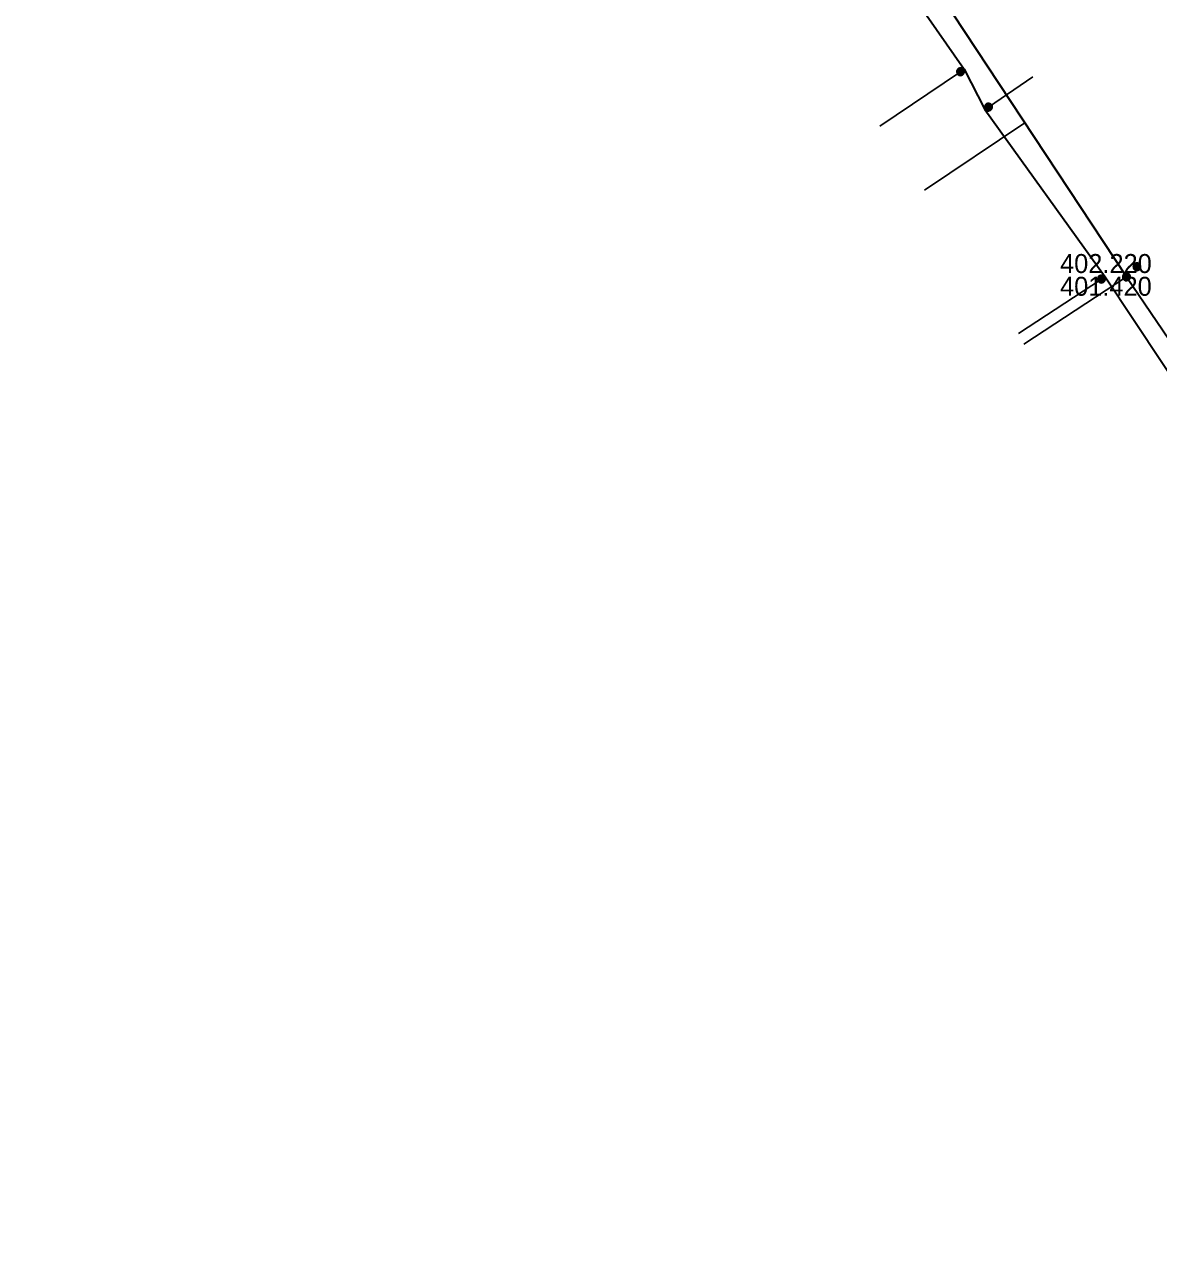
# Model space of a CAD drawing. Extents: x -873619 to -867639, y -1015082 to -1012326.
# Drawn here: x -867979.2 to -867913.4, y -1012931.2 to -1012860 of the extents above; entities that cross this region are included whole.
import ezdxf

# ---------------------------------------------------------------- set-up
doc = ezdxf.new("R2010")
doc.units = 0
doc.header["$LTSCALE"] = 0.44
for name, color, linetype, lineweight in [('1', 7, 'Continuous', 13), ('12', 7, 'Continuous', 13), ('21', 7, 'Continuous', 35), ('23', 7, 'Continuous', 25), ('25', 7, 'Continuous', 13), ('3', 7, 'Continuous', 25), ('32', 7, 'Continuous', 13)]:
    doc.layers.add(name, color=color, linetype=linetype, lineweight=lineweight)

msp = doc.modelspace()

# ---------------------------------------------------------------- linework, layer by layer
at = {"layer": '1', "lineweight": 35}
msp.add_lwpolyline([(-867979.181, -1012799.683), (-867972.83, -1012801.89), (-867965.59, -1012804.78), (-867963.787, -1012807.409), (-867948.768, -1012827.087), (-867948.538, -1012827.407), (-867943.513, -1012834.828), (-867938.476, -1012842.701), (-867934.013, -1012848.778), (-867931.689, -1012852.506), (-867924.702, -1012862.569), (-867923.496, -1012864.901), (-867916.531, -1012874.592), (-867908.231, -1012887.091), (-867905.717, -1012890.99), (-867899.122, -1012900.29), (-867892.55, -1012910.082), (-867889.71, -1012914.412), (-867888.18, -1012916.7), (-867891.84, -1012919), (-867886.89, -1012927.31), (-867886.728, -1012931.158)], dxfattribs=at)
at = {"layer": '12'}
for points in [[(-867924.679, -1012862.71), (-867924.685, -1012862.658), (-867924.702, -1012862.608), (-867924.731, -1012862.564), (-867924.768, -1012862.527), (-867924.813, -1012862.5), (-867924.863, -1012862.483), (-867924.916, -1012862.479), (-867924.968, -1012862.486), (-867925.017, -1012862.505), (-867925.06, -1012862.534), (-867925.096, -1012862.573), (-867925.122, -1012862.618), (-867925.138, -1012862.669), (-867925.141, -1012862.721), (-867925.133, -1012862.773), (-867925.113, -1012862.822), (-867925.082, -1012862.865), (-867925.043, -1012862.899), (-867924.997, -1012862.925), (-867924.946, -1012862.939), (-867924.893, -1012862.941), (-867924.842, -1012862.931), (-867924.794, -1012862.91), (-867924.751, -1012862.879), (-867924.717, -1012862.838), (-867924.693, -1012862.792), (-867924.681, -1012862.741)], [(-867924.709, -1012862.71), (-867924.715, -1012862.661), (-867924.732, -1012862.615), (-867924.76, -1012862.575), (-867924.797, -1012862.543), (-867924.841, -1012862.521), (-867924.889, -1012862.51), (-867924.938, -1012862.51), (-867924.985, -1012862.523), (-867925.028, -1012862.547), (-867925.064, -1012862.58), (-867925.091, -1012862.621), (-867925.107, -1012862.668), (-867925.111, -1012862.717), (-867925.104, -1012862.765), (-867925.085, -1012862.81), (-867925.055, -1012862.85), (-867925.017, -1012862.881), (-867924.973, -1012862.901), (-867924.925, -1012862.911), (-867924.876, -1012862.909), (-867924.829, -1012862.894), (-867924.786, -1012862.869), (-867924.752, -1012862.835), (-867924.726, -1012862.793), (-867924.712, -1012862.746)], [(-867924.739, -1012862.71), (-867924.745, -1012862.665), (-867924.762, -1012862.623), (-867924.79, -1012862.588), (-867924.826, -1012862.561), (-867924.868, -1012862.544), (-867924.913, -1012862.539), (-867924.958, -1012862.545), (-867924.999, -1012862.564), (-867925.034, -1012862.592), (-867925.061, -1012862.629), (-867925.077, -1012862.671), (-867925.081, -1012862.716), (-867925.074, -1012862.761), (-867925.055, -1012862.802), (-867925.026, -1012862.836), (-867924.989, -1012862.862), (-867924.946, -1012862.878), (-867924.901, -1012862.881), (-867924.856, -1012862.873), (-867924.816, -1012862.853), (-867924.782, -1012862.824), (-867924.756, -1012862.786), (-867924.742, -1012862.743)], [(-867924.769, -1012862.71), (-867924.774, -1012862.669), (-867924.792, -1012862.632), (-867924.819, -1012862.601), (-867924.854, -1012862.58), (-867924.894, -1012862.569), (-867924.935, -1012862.571), (-867924.974, -1012862.584), (-867925.008, -1012862.608), (-867925.033, -1012862.64), (-867925.048, -1012862.678), (-867925.051, -1012862.719), (-867925.043, -1012862.759), (-867925.023, -1012862.795), (-867924.994, -1012862.824), (-867924.957, -1012862.843), (-867924.917, -1012862.851), (-867924.876, -1012862.847), (-867924.838, -1012862.832), (-867924.806, -1012862.806), (-867924.783, -1012862.772), (-867924.77, -1012862.733)], [(-867924.799, -1012862.71), (-867924.804, -1012862.674), (-867924.822, -1012862.642), (-867924.848, -1012862.617), (-867924.882, -1012862.602), (-867924.918, -1012862.599), (-867924.953, -1012862.607), (-867924.984, -1012862.627), (-867925.007, -1012862.655), (-867925.02, -1012862.689), (-867925.02, -1012862.726), (-867925.009, -1012862.761), (-867924.988, -1012862.79), (-867924.958, -1012862.811), (-867924.923, -1012862.821), (-867924.886, -1012862.819), (-867924.852, -1012862.805), (-867924.825, -1012862.782), (-867924.806, -1012862.75), (-867924.799, -1012862.715)], [(-867924.829, -1012862.71), (-867924.834, -1012862.679), (-867924.851, -1012862.653), (-867924.877, -1012862.636), (-867924.907, -1012862.629), (-867924.938, -1012862.633), (-867924.965, -1012862.65), (-867924.983, -1012862.674), (-867924.991, -1012862.705), (-867924.987, -1012862.735), (-867924.972, -1012862.763), (-867924.948, -1012862.782), (-867924.918, -1012862.791), (-867924.887, -1012862.788), (-867924.859, -1012862.774), (-867924.839, -1012862.75), (-867924.829, -1012862.721)], [(-867924.859, -1012862.71), (-867924.864, -1012862.686), (-867924.881, -1012862.668), (-867924.904, -1012862.659), (-867924.928, -1012862.662), (-867924.949, -1012862.676), (-867924.96, -1012862.698), (-867924.96, -1012862.723), (-867924.948, -1012862.744), (-867924.928, -1012862.758), (-867924.903, -1012862.761), (-867924.88, -1012862.752), (-867924.864, -1012862.734)], [(-867924.889, -1012862.71), (-867924.894, -1012862.695), (-867924.909, -1012862.689), (-867924.924, -1012862.693), (-867924.931, -1012862.707), (-867924.927, -1012862.722), (-867924.914, -1012862.731), (-867924.899, -1012862.728), (-867924.889, -1012862.716)], [(-867923.059, -1012864.759), (-867923.066, -1012864.707), (-867923.083, -1012864.657), (-867923.112, -1012864.613), (-867923.149, -1012864.576), (-867923.194, -1012864.549), (-867923.244, -1012864.532), (-867923.297, -1012864.528), (-867923.348, -1012864.535), (-867923.397, -1012864.554), (-867923.441, -1012864.583), (-867923.477, -1012864.622), (-867923.503, -1012864.667), (-867923.519, -1012864.718), (-867923.522, -1012864.77), (-867923.514, -1012864.822), (-867923.494, -1012864.871), (-867923.463, -1012864.914), (-867923.424, -1012864.948), (-867923.378, -1012864.974), (-867923.326, -1012864.988), (-867923.274, -1012864.99), (-867923.223, -1012864.98), (-867923.174, -1012864.959), (-867923.132, -1012864.928), (-867923.098, -1012864.887), (-867923.074, -1012864.841), (-867923.061, -1012864.79)], [(-867923.09, -1012864.759), (-867923.096, -1012864.71), (-867923.113, -1012864.664), (-867923.141, -1012864.624), (-867923.178, -1012864.592), (-867923.222, -1012864.57), (-867923.27, -1012864.559), (-867923.319, -1012864.559), (-867923.365, -1012864.572), (-867923.409, -1012864.596), (-867923.445, -1012864.629), (-867923.472, -1012864.67), (-867923.488, -1012864.717), (-867923.492, -1012864.766), (-867923.485, -1012864.814), (-867923.466, -1012864.859), (-867923.436, -1012864.899), (-867923.397, -1012864.93), (-867923.353, -1012864.95), (-867923.306, -1012864.96), (-867923.257, -1012864.958), (-867923.21, -1012864.943), (-867923.167, -1012864.918), (-867923.132, -1012864.884), (-867923.107, -1012864.842), (-867923.093, -1012864.795)], [(-867923.12, -1012864.759), (-867923.125, -1012864.714), (-867923.142, -1012864.672), (-867923.171, -1012864.637), (-867923.206, -1012864.61), (-867923.249, -1012864.593), (-867923.294, -1012864.588), (-867923.338, -1012864.594), (-867923.38, -1012864.613), (-867923.414, -1012864.641), (-867923.441, -1012864.678), (-867923.458, -1012864.72), (-867923.462, -1012864.765), (-867923.455, -1012864.81), (-867923.436, -1012864.851), (-867923.407, -1012864.885), (-867923.37, -1012864.911), (-867923.326, -1012864.927), (-867923.282, -1012864.93), (-867923.237, -1012864.922), (-867923.196, -1012864.902), (-867923.163, -1012864.873), (-867923.137, -1012864.835), (-867923.123, -1012864.792)], [(-867923.15, -1012864.759), (-867923.154, -1012864.718), (-867923.173, -1012864.681), (-867923.2, -1012864.65), (-867923.235, -1012864.629), (-867923.275, -1012864.618), (-867923.316, -1012864.62), (-867923.355, -1012864.633), (-867923.389, -1012864.657), (-867923.414, -1012864.689), (-867923.429, -1012864.727), (-867923.431, -1012864.768), (-867923.424, -1012864.808), (-867923.404, -1012864.844), (-867923.375, -1012864.873), (-867923.338, -1012864.892), (-867923.298, -1012864.9), (-867923.257, -1012864.896), (-867923.218, -1012864.881), (-867923.186, -1012864.855), (-867923.164, -1012864.821), (-867923.151, -1012864.782)], [(-867923.179, -1012864.759), (-867923.184, -1012864.723), (-867923.203, -1012864.691), (-867923.228, -1012864.666), (-867923.262, -1012864.651), (-867923.299, -1012864.648), (-867923.333, -1012864.656), (-867923.365, -1012864.676), (-867923.387, -1012864.704), (-867923.401, -1012864.738), (-867923.401, -1012864.775), (-867923.39, -1012864.81), (-867923.369, -1012864.839), (-867923.338, -1012864.86), (-867923.304, -1012864.87), (-867923.267, -1012864.868), (-867923.233, -1012864.854), (-867923.206, -1012864.831), (-867923.186, -1012864.799), (-867923.179, -1012864.764)], [(-867923.21, -1012864.759), (-867923.215, -1012864.728), (-867923.232, -1012864.702), (-867923.257, -1012864.685), (-867923.288, -1012864.678), (-867923.319, -1012864.682), (-867923.346, -1012864.699), (-867923.364, -1012864.723), (-867923.372, -1012864.754), (-867923.368, -1012864.784), (-867923.353, -1012864.812), (-867923.328, -1012864.831), (-867923.299, -1012864.84), (-867923.267, -1012864.837), (-867923.24, -1012864.823), (-867923.22, -1012864.799), (-867923.21, -1012864.77)], [(-867923.24, -1012864.759), (-867923.245, -1012864.735), (-867923.262, -1012864.717), (-867923.284, -1012864.708), (-867923.309, -1012864.711), (-867923.33, -1012864.725), (-867923.341, -1012864.747), (-867923.341, -1012864.772), (-867923.328, -1012864.793), (-867923.309, -1012864.807), (-867923.284, -1012864.81), (-867923.261, -1012864.801), (-867923.245, -1012864.783)], [(-867923.27, -1012864.759), (-867923.275, -1012864.744), (-867923.289, -1012864.738), (-867923.304, -1012864.742), (-867923.311, -1012864.756), (-867923.308, -1012864.771), (-867923.294, -1012864.78), (-867923.279, -1012864.777), (-867923.27, -1012864.765)], [(-867916.507, -1012874.728), (-867916.514, -1012874.676), (-867916.531, -1012874.626), (-867916.559, -1012874.582), (-867916.597, -1012874.545), (-867916.642, -1012874.518), (-867916.691, -1012874.501), (-867916.745, -1012874.497), (-867916.796, -1012874.504), (-867916.845, -1012874.523), (-867916.889, -1012874.552), (-867916.924, -1012874.591), (-867916.951, -1012874.636), (-867916.967, -1012874.687), (-867916.97, -1012874.739), (-867916.962, -1012874.791), (-867916.941, -1012874.84), (-867916.911, -1012874.883), (-867916.872, -1012874.917), (-867916.826, -1012874.943), (-867916.774, -1012874.957), (-867916.722, -1012874.959), (-867916.671, -1012874.949), (-867916.622, -1012874.928), (-867916.58, -1012874.897), (-867916.546, -1012874.856), (-867916.522, -1012874.81), (-867916.509, -1012874.759)], [(-867916.538, -1012874.728), (-867916.544, -1012874.679), (-867916.561, -1012874.633), (-867916.588, -1012874.593), (-867916.625, -1012874.561), (-867916.669, -1012874.539), (-867916.718, -1012874.528), (-867916.767, -1012874.528), (-867916.813, -1012874.541), (-867916.857, -1012874.565), (-867916.892, -1012874.598), (-867916.919, -1012874.639), (-867916.936, -1012874.686), (-867916.94, -1012874.735), (-867916.933, -1012874.783), (-867916.914, -1012874.828), (-867916.884, -1012874.868), (-867916.845, -1012874.899), (-867916.801, -1012874.919), (-867916.754, -1012874.929), (-867916.705, -1012874.927), (-867916.657, -1012874.912), (-867916.615, -1012874.887), (-867916.58, -1012874.853), (-867916.554, -1012874.811), (-867916.541, -1012874.764)], [(-867916.568, -1012874.728), (-867916.573, -1012874.683), (-867916.59, -1012874.641), (-867916.619, -1012874.606), (-867916.654, -1012874.579), (-867916.696, -1012874.562), (-867916.742, -1012874.557), (-867916.786, -1012874.563), (-867916.828, -1012874.582), (-867916.862, -1012874.61), (-867916.889, -1012874.647), (-867916.906, -1012874.689), (-867916.909, -1012874.734), (-867916.902, -1012874.779), (-867916.884, -1012874.82), (-867916.855, -1012874.854), (-867916.818, -1012874.88), (-867916.774, -1012874.896), (-867916.73, -1012874.899), (-867916.684, -1012874.891), (-867916.644, -1012874.871), (-867916.61, -1012874.842), (-867916.585, -1012874.804), (-867916.571, -1012874.761)], [(-867916.598, -1012874.728), (-867916.602, -1012874.687), (-867916.62, -1012874.65), (-867916.647, -1012874.619), (-867916.683, -1012874.598), (-867916.723, -1012874.587), (-867916.764, -1012874.589), (-867916.803, -1012874.602), (-867916.837, -1012874.626), (-867916.862, -1012874.658), (-867916.877, -1012874.696), (-867916.879, -1012874.737), (-867916.872, -1012874.777), (-867916.852, -1012874.813), (-867916.823, -1012874.842), (-867916.786, -1012874.861), (-867916.745, -1012874.869), (-867916.705, -1012874.865), (-867916.666, -1012874.85), (-867916.634, -1012874.824), (-867916.612, -1012874.79), (-867916.598, -1012874.751)], [(-867916.627, -1012874.728), (-867916.632, -1012874.692), (-867916.651, -1012874.66), (-867916.676, -1012874.635), (-867916.71, -1012874.62), (-867916.747, -1012874.617), (-867916.781, -1012874.625), (-867916.813, -1012874.645), (-867916.835, -1012874.673), (-867916.848, -1012874.707), (-867916.848, -1012874.744), (-867916.838, -1012874.779), (-867916.816, -1012874.808), (-867916.786, -1012874.829), (-867916.752, -1012874.839), (-867916.715, -1012874.837), (-867916.681, -1012874.823), (-867916.654, -1012874.8), (-867916.634, -1012874.768), (-867916.627, -1012874.733)], [(-867916.657, -1012874.728), (-867916.663, -1012874.697), (-867916.679, -1012874.671), (-867916.705, -1012874.654), (-867916.735, -1012874.647), (-867916.767, -1012874.651), (-867916.794, -1012874.668), (-867916.811, -1012874.692), (-867916.82, -1012874.723), (-867916.816, -1012874.753), (-867916.801, -1012874.781), (-867916.776, -1012874.8), (-867916.747, -1012874.809), (-867916.715, -1012874.806), (-867916.688, -1012874.792), (-867916.668, -1012874.768), (-867916.657, -1012874.739)], [(-867916.688, -1012874.728), (-867916.693, -1012874.704), (-867916.71, -1012874.686), (-867916.732, -1012874.677), (-867916.757, -1012874.68), (-867916.777, -1012874.694), (-867916.789, -1012874.716), (-867916.789, -1012874.741), (-867916.776, -1012874.762), (-867916.757, -1012874.776), (-867916.732, -1012874.779), (-867916.708, -1012874.77), (-867916.693, -1012874.752)], [(-867916.718, -1012874.728), (-867916.723, -1012874.713), (-867916.737, -1012874.707), (-867916.752, -1012874.711), (-867916.759, -1012874.725), (-867916.755, -1012874.74), (-867916.742, -1012874.749), (-867916.727, -1012874.746), (-867916.718, -1012874.734)]]:
    msp.add_lwpolyline(points, close=True, dxfattribs=at)
at = {"layer": '21'}
for p, q in [((-867952.038, -1012818.911), (-867915.289, -1012874.6)), ((-867915.29, -1012874.6), (-867889.85, -1012912.11))]:
    msp.add_line(p, q, dxfattribs=at)
at = {"layer": '23'}
for p, q in [((-867921.182, -1012865.665), (-867927, -1012869.58)), ((-867915.29, -1012874.6), (-867921.24, -1012878.5))]:
    msp.add_line(p, q, dxfattribs=at)
at = {"layer": '25'}
for points in [[(-867914.449, -1012874.02), (-867914.455, -1012873.968), (-867914.472, -1012873.918), (-867914.501, -1012873.874), (-867914.538, -1012873.837), (-867914.583, -1012873.81), (-867914.633, -1012873.793), (-867914.686, -1012873.789), (-867914.738, -1012873.796), (-867914.787, -1012873.815), (-867914.83, -1012873.844), (-867914.866, -1012873.883), (-867914.892, -1012873.928), (-867914.908, -1012873.979), (-867914.911, -1012874.031), (-867914.903, -1012874.083), (-867914.883, -1012874.132), (-867914.852, -1012874.175), (-867914.813, -1012874.209), (-867914.767, -1012874.235), (-867914.716, -1012874.249), (-867914.663, -1012874.251), (-867914.612, -1012874.241), (-867914.564, -1012874.22), (-867914.521, -1012874.189), (-867914.487, -1012874.148), (-867914.463, -1012874.102), (-867914.451, -1012874.051)], [(-867914.479, -1012874.02), (-867914.485, -1012873.971), (-867914.502, -1012873.925), (-867914.53, -1012873.885), (-867914.567, -1012873.853), (-867914.611, -1012873.831), (-867914.659, -1012873.82), (-867914.708, -1012873.82), (-867914.755, -1012873.833), (-867914.798, -1012873.857), (-867914.834, -1012873.89), (-867914.861, -1012873.931), (-867914.877, -1012873.978), (-867914.881, -1012874.027), (-867914.874, -1012874.075), (-867914.855, -1012874.12), (-867914.825, -1012874.16), (-867914.787, -1012874.191), (-867914.743, -1012874.211), (-867914.695, -1012874.221), (-867914.646, -1012874.219), (-867914.599, -1012874.204), (-867914.556, -1012874.179), (-867914.522, -1012874.145), (-867914.496, -1012874.103), (-867914.482, -1012874.056)], [(-867914.509, -1012874.02), (-867914.515, -1012873.975), (-867914.532, -1012873.933), (-867914.56, -1012873.898), (-867914.596, -1012873.871), (-867914.638, -1012873.854), (-867914.683, -1012873.849), (-867914.728, -1012873.855), (-867914.769, -1012873.874), (-867914.804, -1012873.902), (-867914.831, -1012873.939), (-867914.847, -1012873.981), (-867914.851, -1012874.026), (-867914.844, -1012874.071), (-867914.825, -1012874.112), (-867914.796, -1012874.146), (-867914.759, -1012874.172), (-867914.716, -1012874.188), (-867914.671, -1012874.191), (-867914.626, -1012874.183), (-867914.586, -1012874.163), (-867914.552, -1012874.134), (-867914.526, -1012874.096), (-867914.512, -1012874.053)], [(-867914.539, -1012874.02), (-867914.544, -1012873.979), (-867914.562, -1012873.942), (-867914.589, -1012873.911), (-867914.624, -1012873.89), (-867914.664, -1012873.879), (-867914.705, -1012873.881), (-867914.744, -1012873.894), (-867914.778, -1012873.918), (-867914.803, -1012873.95), (-867914.818, -1012873.988), (-867914.821, -1012874.029), (-867914.813, -1012874.069), (-867914.793, -1012874.105), (-867914.764, -1012874.134), (-867914.727, -1012874.153), (-867914.687, -1012874.161), (-867914.646, -1012874.157), (-867914.608, -1012874.142), (-867914.576, -1012874.116), (-867914.553, -1012874.082), (-867914.54, -1012874.043)], [(-867914.569, -1012874.02), (-867914.574, -1012873.984), (-867914.592, -1012873.952), (-867914.618, -1012873.927), (-867914.652, -1012873.912), (-867914.688, -1012873.909), (-867914.723, -1012873.917), (-867914.754, -1012873.937), (-867914.777, -1012873.965), (-867914.79, -1012873.999), (-867914.79, -1012874.036), (-867914.779, -1012874.071), (-867914.758, -1012874.1), (-867914.728, -1012874.121), (-867914.693, -1012874.131), (-867914.656, -1012874.129), (-867914.622, -1012874.115), (-867914.595, -1012874.092), (-867914.576, -1012874.06), (-867914.569, -1012874.025)], [(-867914.599, -1012874.02), (-867914.604, -1012873.989), (-867914.621, -1012873.963), (-867914.647, -1012873.946), (-867914.677, -1012873.939), (-867914.708, -1012873.943), (-867914.735, -1012873.96), (-867914.753, -1012873.984), (-867914.761, -1012874.015), (-867914.757, -1012874.045), (-867914.742, -1012874.073), (-867914.718, -1012874.092), (-867914.688, -1012874.101), (-867914.657, -1012874.098), (-867914.629, -1012874.084), (-867914.609, -1012874.06), (-867914.599, -1012874.031)], [(-867914.629, -1012874.02), (-867914.634, -1012873.996), (-867914.651, -1012873.978), (-867914.674, -1012873.969), (-867914.698, -1012873.972), (-867914.719, -1012873.986), (-867914.73, -1012874.008), (-867914.73, -1012874.033), (-867914.718, -1012874.054), (-867914.698, -1012874.068), (-867914.673, -1012874.071), (-867914.65, -1012874.062), (-867914.634, -1012874.044)], [(-867914.659, -1012874.02), (-867914.664, -1012874.005), (-867914.679, -1012873.999), (-867914.694, -1012874.003), (-867914.701, -1012874.017), (-867914.697, -1012874.032), (-867914.684, -1012874.041), (-867914.669, -1012874.038), (-867914.659, -1012874.026)]]:
    msp.add_lwpolyline(points, close=True, dxfattribs=at)
at = {"layer": '3'}
for points in [[(-867924.702, -1012862.569), (-867924.91, -1012862.71), (-867929.587, -1012865.873)], [(-867923.496, -1012864.901), (-867923.29, -1012864.76), (-867920.726, -1012863)], [(-867916.531, -1012874.592), (-867916.74, -1012874.73), (-867921.554, -1012877.893)]]:
    msp.add_lwpolyline(points, dxfattribs=at)
at = {"layer": '32'}
for points in [[(-867915.059, -1012874.6), (-867915.065, -1012874.548), (-867915.082, -1012874.498), (-867915.111, -1012874.454), (-867915.148, -1012874.417), (-867915.193, -1012874.39), (-867915.243, -1012874.373), (-867915.296, -1012874.369), (-867915.348, -1012874.376), (-867915.397, -1012874.395), (-867915.44, -1012874.424), (-867915.476, -1012874.463), (-867915.502, -1012874.508), (-867915.518, -1012874.559), (-867915.521, -1012874.611), (-867915.513, -1012874.663), (-867915.493, -1012874.712), (-867915.462, -1012874.755), (-867915.423, -1012874.789), (-867915.377, -1012874.815), (-867915.326, -1012874.829), (-867915.273, -1012874.831), (-867915.222, -1012874.821), (-867915.174, -1012874.8), (-867915.131, -1012874.769), (-867915.097, -1012874.728), (-867915.073, -1012874.682), (-867915.061, -1012874.631)], [(-867915.089, -1012874.6), (-867915.095, -1012874.551), (-867915.112, -1012874.505), (-867915.14, -1012874.465), (-867915.177, -1012874.433), (-867915.221, -1012874.411), (-867915.269, -1012874.4), (-867915.318, -1012874.4), (-867915.365, -1012874.413), (-867915.408, -1012874.437), (-867915.444, -1012874.47), (-867915.471, -1012874.511), (-867915.487, -1012874.558), (-867915.491, -1012874.607), (-867915.484, -1012874.655), (-867915.465, -1012874.7), (-867915.435, -1012874.74), (-867915.397, -1012874.771), (-867915.353, -1012874.791), (-867915.305, -1012874.801), (-867915.256, -1012874.799), (-867915.209, -1012874.784), (-867915.166, -1012874.759), (-867915.132, -1012874.725), (-867915.106, -1012874.683), (-867915.092, -1012874.636)], [(-867915.119, -1012874.6), (-867915.125, -1012874.555), (-867915.142, -1012874.513), (-867915.17, -1012874.478), (-867915.206, -1012874.451), (-867915.248, -1012874.434), (-867915.293, -1012874.429), (-867915.338, -1012874.435), (-867915.379, -1012874.454), (-867915.414, -1012874.482), (-867915.441, -1012874.519), (-867915.457, -1012874.561), (-867915.461, -1012874.606), (-867915.454, -1012874.651), (-867915.435, -1012874.692), (-867915.406, -1012874.726), (-867915.369, -1012874.752), (-867915.326, -1012874.768), (-867915.281, -1012874.771), (-867915.236, -1012874.763), (-867915.196, -1012874.743), (-867915.162, -1012874.714), (-867915.136, -1012874.676), (-867915.122, -1012874.633)], [(-867915.149, -1012874.6), (-867915.154, -1012874.559), (-867915.172, -1012874.522), (-867915.199, -1012874.491), (-867915.234, -1012874.47), (-867915.274, -1012874.459), (-867915.315, -1012874.461), (-867915.354, -1012874.474), (-867915.388, -1012874.498), (-867915.413, -1012874.53), (-867915.428, -1012874.568), (-867915.431, -1012874.609), (-867915.423, -1012874.649), (-867915.403, -1012874.685), (-867915.374, -1012874.714), (-867915.337, -1012874.733), (-867915.297, -1012874.741), (-867915.256, -1012874.737), (-867915.218, -1012874.722), (-867915.186, -1012874.696), (-867915.163, -1012874.662), (-867915.15, -1012874.623)], [(-867915.179, -1012874.6), (-867915.184, -1012874.564), (-867915.202, -1012874.532), (-867915.228, -1012874.507), (-867915.262, -1012874.492), (-867915.298, -1012874.489), (-867915.333, -1012874.497), (-867915.364, -1012874.517), (-867915.387, -1012874.545), (-867915.4, -1012874.579), (-867915.4, -1012874.616), (-867915.389, -1012874.651), (-867915.368, -1012874.68), (-867915.338, -1012874.701), (-867915.303, -1012874.711), (-867915.266, -1012874.709), (-867915.232, -1012874.695), (-867915.205, -1012874.672), (-867915.186, -1012874.64), (-867915.179, -1012874.605)], [(-867915.209, -1012874.6), (-867915.214, -1012874.569), (-867915.231, -1012874.543), (-867915.257, -1012874.526), (-867915.287, -1012874.519), (-867915.318, -1012874.523), (-867915.345, -1012874.54), (-867915.363, -1012874.564), (-867915.371, -1012874.595), (-867915.367, -1012874.625), (-867915.352, -1012874.653), (-867915.328, -1012874.672), (-867915.298, -1012874.681), (-867915.267, -1012874.678), (-867915.239, -1012874.664), (-867915.219, -1012874.64), (-867915.209, -1012874.611)], [(-867915.239, -1012874.6), (-867915.244, -1012874.576), (-867915.261, -1012874.558), (-867915.284, -1012874.549), (-867915.308, -1012874.552), (-867915.329, -1012874.566), (-867915.34, -1012874.588), (-867915.34, -1012874.613), (-867915.328, -1012874.634), (-867915.308, -1012874.648), (-867915.283, -1012874.651), (-867915.26, -1012874.642), (-867915.244, -1012874.624)], [(-867915.269, -1012874.6), (-867915.274, -1012874.585), (-867915.289, -1012874.579), (-867915.304, -1012874.583), (-867915.311, -1012874.597), (-867915.307, -1012874.612), (-867915.294, -1012874.621), (-867915.279, -1012874.618), (-867915.269, -1012874.606)]]:
    msp.add_lwpolyline(points, close=True, dxfattribs=at)

# ---------------------------------------------------------------- texts
at = {"layer": '1'}
for s, p in [('402.220 ', (-867919.14, -1012874.38)), ('401.420 ', (-867919.14, -1012875.7))]:
    msp.add_text(s, height=1.1, dxfattribs=at).set_placement(p)

doc.saveas('drawing.dxf')
